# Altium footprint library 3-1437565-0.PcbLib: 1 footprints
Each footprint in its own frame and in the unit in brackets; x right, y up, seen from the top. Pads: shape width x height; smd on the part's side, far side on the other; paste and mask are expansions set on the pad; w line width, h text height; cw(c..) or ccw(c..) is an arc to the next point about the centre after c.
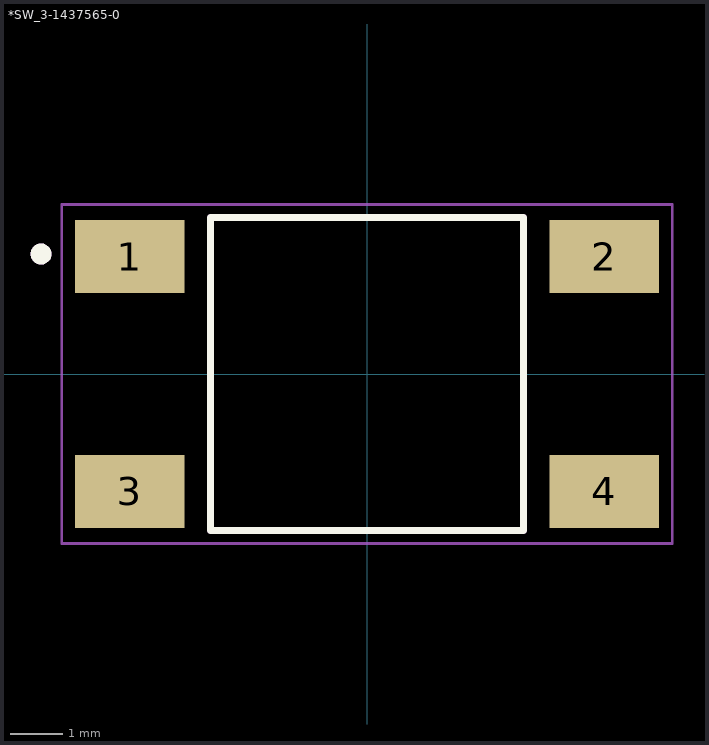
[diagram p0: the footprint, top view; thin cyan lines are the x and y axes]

## *SW_3-1437565-0 [mm]
pads (4):
  rect 2.1x1.4 smd: 1(-4.55,2.25) 2(4.55,2.25) 3(-4.55,-2.25) 4(4.55,-2.25)
Top Overlay:
  circle w0.2: c-6.25,2.3 r0.1
  lines w0.127: -3,-3 -3,3 3,3 3,-3 -3,-3
Mechanical 4:
  circle w0.2: c-6.25,2.3 r0.1
  circle w0.2: c-6.25,2.3 r0.1
  lines w0.127: -3,-3 3,-3 ; -3,-3 -3,3 ; -3,-3 3,-3 ; -3,-3 -3,3 ; -3,3 3,3 ; -3,3 3,3 ; 3,-3 3,3 ; 3,-3 3,3
Mechanical 16:
  lines w0.05: -5.85,-3.25 5.85,-3.25 5.85,3.25 -5.85,3.25 -5.85,-3.25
